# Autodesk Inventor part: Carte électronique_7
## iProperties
Created: 2010-07
Part Number: Carte électronique_7
Document SubType Name: Modeling
Designer: eric
Density: 1 g/cm^3
Author: eric
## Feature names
1. Base1
